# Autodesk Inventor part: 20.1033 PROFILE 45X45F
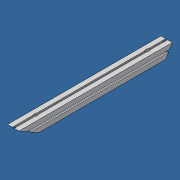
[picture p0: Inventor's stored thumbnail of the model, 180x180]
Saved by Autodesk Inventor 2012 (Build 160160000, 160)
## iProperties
Created: 2015-01
Part Number: 20.1033 PROFILE 45X45F
Material: Aluminum-6061
Description: L = SPECIFY MILL TO 21.9431/C
Document SubType Name: Modeling
Designer: Admin
Density: 2.71 g/cm^3
Mass: 2365.65 g
Surface Area: 6366.41 cm^2
Volume: 872.933 cm^3
Vendor: F
FINISH: CLEAR ANODIZED
Author: Admin
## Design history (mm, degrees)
sketch "Sketch1"
  geometry: L1 (-4.1, -22.5)-(-4.1, -18) reference; L2 (-4.6, -18)-(-6.8, -18) reference; L3 (-6.8, -18)-(-6.8, -9.5) reference; L4 (-6.8, -9.5)-(-4.5, -7.2) reference; L5 (-4.5, -7.2)-(4.5, -7.2) reference; L6 (4.5, -7.2)-(6.8, -9.5) reference; L7 (6.8, -9.5)-(6.8, -18) reference; L8 (4.1, -18)-(4.1, -22.5) reference; L9 (22.5, -4.1)-(18, -4.1) reference; L10 (18, -4.6)-(18, -6.8) reference; L11 (18, -6.8)-(9.5, -6.8) reference; L12 (9.5, -6.8)-(7.2, -4.5) reference; L13 (7.2, -4.5)-(7.2, 4.5) reference; L14 (7.2, 4.5)-(9.5, 6.8) reference; L15 (9.5, 6.8)-(18, 6.8) reference; L16 (18, 4.1)-(22.5, 4.1) reference; L17 (22.5, 22.5)-(22.5, 4.4) reference; L18 (4.1, 22.5)-(4.1, 18) reference; L19 (4.6, 18)-(6.8, 18) reference; L20 (6.8, 18)-(6.8, 9.5) reference; L21 (6.8, 9.5)-(4.5, 7.2) reference; L22 (4.5, 7.2)-(-4.5, 7.2) reference; L23 (-4.5, 7.2)-(-6.8, 9.5) reference; L24 (-6.8, 9.5)-(-6.8, 18) reference; L25 (-4.1, 18)-(-4.1, 22.5) reference; L26 (-22.5, 22.5)-(-4.4, 22.5) reference; L27 (-22.5, 4.1)-(-18, 4.1) reference; L28 (-18, 6.8)-(-9.5, 6.8) reference; L29 (-9.5, 6.8)-(-7.2, 4.5) reference; L30 (-7.2, 4.5)-(-7.2, -4.5) reference; L31 (-7.2, -4.5)-(-9.5, -6.8) reference; L32 (-9.5, -6.8)-(-18, -6.8) reference; L33 (-18, -6.8)-(-18, -4.6) reference; L34 (-18, -4.1)-(-22.5, -4.1) reference; L35 (-22.5, -22.5)-(-22.5, -4.4) reference; L36 (-4.4, -22.5)-(-22.5, -22.5) reference; L37 (-4.596, -3.182)-(-3.263, -1.849) reference; L38 (-3.263, 1.849)-(-4.596, 3.182) reference; L39 (-4.596, 3.182)-(-3.182, 4.596) reference; L40 (-3.182, 4.596)-(-1.849, 3.263) reference; L41 (1.849, 3.263)-(3.182, 4.596) reference; L42 (3.182, 4.596)-(4.596, 3.182) reference; L43 (4.596, 3.182)-(3.263, 1.849) reference; L44 (3.263, -1.849)-(4.596, -3.182) reference; L45 (4.596, -3.182)-(3.182, -4.596) reference; L46 (3.182, -4.596)-(1.849, -3.263) reference; L47 (-1.849, -3.263)-(-3.182, -4.596) reference; L48 (-3.182, -4.596)-(-4.596, -3.182) reference; L49 (13.8, -8.8)-(20.5, -8.8) reference; L50 (20.5, -8.8)-(20.5, -15.5) reference; L51 (15.5, -20.5)-(8.8, -20.5) reference; L52 (8.8, -20.5)-(8.8, -13.8) reference; L53 (8.8, 13.8)-(8.8, 20.5) reference; L54 (8.8, 20.5)-(15.5, 20.5) reference; L55 (20.5, 15.5)-(20.5, 8.8) reference; L56 (20.5, 8.8)-(13.8, 8.8) reference; L57 (-13.8, 8.8)-(-20.5, 8.8) reference; L58 (-20.5, 8.8)-(-20.5, 15.5) reference; L59 (-15.5, 20.5)-(-8.8, 20.5) reference; L60 (-8.8, 20.5)-(-8.8, 13.8) reference; L61 (-8.8, -13.8)-(-8.8, -20.5) reference; L62 (-8.8, -20.5)-(-15.5, -20.5) reference; L63 (-20.5, -15.5)-(-20.5, -8.8) reference; L64 (-20.5, -8.8)-(-13.8, -8.8) reference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; A1 r 3.75 centre (0, 0) between (3.362, -1.66) and (3.362, 1.66) reference; A2 r 5 centre (13.8, -13.8) between (13.8, -8.8) and (8.8, -13.8) reference; A3 r 5 centre (15.5, -15.5) between (15.5, -20.5) and (20.5, -15.5) reference; A4 r 5 centre (13.8, 13.8) between (8.8, 13.8) and (13.8, 8.8) reference; A5 r 5 centre (15.5, 15.5) between (20.5, 15.5) and (15.5, 20.5) reference; A6 r 5 centre (-13.8, 13.8) between (-13.8, 8.8) and (-8.8, 13.8) reference; A7 r 5 centre (-15.5, 15.5) between (-15.5, 20.5) and (-20.5, 15.5) reference; A8 r 5 centre (-13.8, -13.8) between (-8.8, -13.8) and (-13.8, -8.8) reference; A9 r 5 centre (-15.5, -15.5) between (-20.5, -15.5) and (-15.5, -20.5) reference; A10 r 3.75 centre (0, 0) between (3.362, 1.66) and (3.263, 1.849) reference; A11 r 3.75 centre (0, 0) between (1.849, 3.263) and (-1.66, 3.362) reference; A12 r 3.75 centre (0, 0) between (-1.66, 3.362) and (-1.849, 3.263) reference; A13 r 3.75 centre (0, 0) between (-3.263, 1.849) and (-3.263, -1.849) reference; A14 r 3.75 centre (0, 0) between (-1.849, -3.263) and (-1.66, -3.362) reference; A15 r 3.75 centre (0, 0) between (-1.66, -3.362) and (1.849, -3.263) reference; A16 r 3.75 centre (0, 0) between (3.263, -1.849) and (3.362, -1.66) reference
  constraints: 160 end point, 32 point on circle, 30 horizontal, 30 vertical, 16 centre point, 144 other
extrude "Extrusion1" new body sketch "Sketch1" distance "d0" = 609.6 (= LENGTH); taper "d1" = 0 deg
sketch "Sketch2"
  geometry: L1 (0, -45)-(609.6, -45) reference; L2 (0, 0)-(25.981, -45); L3 (25.981, -45)-(0, -45); L4 (0, -45)-(0, 0); L5 (609.6, 0)-(531.658, -45); L6 (531.658, -45)-(609.6, -45); L7 (609.6, -45)-(609.6, 0); 1 further point
  constraints: 12 end point, 2 collinear, 2 perpendicular, 2 point on line
  dimensions: "d2" = 30 deg angle of L2 L4; "d3" = 30 deg angle of L6 L5
extrude "Extrusion2" cut sketch "Sketch2" distance "d4" = 914.4; taper "d5" = 0 deg
workplane "Work Plane1"
sketch "Sketch3"
  geometry: L1 (18, -30.6)-(27, -30.6) reference; L2 (26.6, 0)-(45, 0) reference; C1 r 4.25 at (22.5, -76.2); 2 further points
  constraints: 1 centre point, 1 midpoint, 1 vertical alignment
  dimensions: "d7" = 8.5 diameter of C1; "d8" = 76.2 distance from line of C1.centre L2
extrude "Extrusion3" cut sketch "Sketch3" stored distance "d9" = 0; taper "d10" = 0 deg
sketch "Sketch4"
  geometry: C1 r 4.25 at (22.5, -76.2) reference; C2 r 6.5 at (22.5, -76.2); 1 further point
  constraints: 1 centre point, 1 coincident
  dimensions: "d11" = 13 diameter of C2
extrude "Extrusion4" cut sketch "Sketch4" distance "d12" = 25.4; taper "d13" = 0 deg
sketch "Sketch5"
  geometry: L1 (18.4, 51.962)-(0, 51.962) reference; C1 r 4.25 at (22.5, 13.862); 4 further points; 1 other entity
  constraints: 1 centre point, 1 vertical alignment, 1 other
  dimensions: "d14" = 8.5 diameter of C1; "d15" = 38.1 distance from line of C1.centre L1
extrude "Extrusion5" cut sketch "Sketch5" distance "d16" = 127; taper "d17" = 0 deg
workplane "Work Plane2"
sketch "Sketch6"
  geometry: C1 r 6.5 at (-4.1, 13.862); A1 r 4.25 centre (-4.1, 13.862) between (-5.992, 17.667) and (-2.208, 17.667) reference; 1 further point
  constraints: 1 centre point, 1 coincident
  dimensions: "d19" = 13 diameter of C1
extrude "Extrusion6" cut sketch "Sketch6" distance "d20" = 127; taper "d21" = 0 deg
body "Solid1"
other parameters: "d6" = -21.59, "d18" = -21.59, "LENGTH" = 609.6 [user parameter; used in 1 equation term]
